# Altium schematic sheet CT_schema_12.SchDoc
size 146 x 119 mm
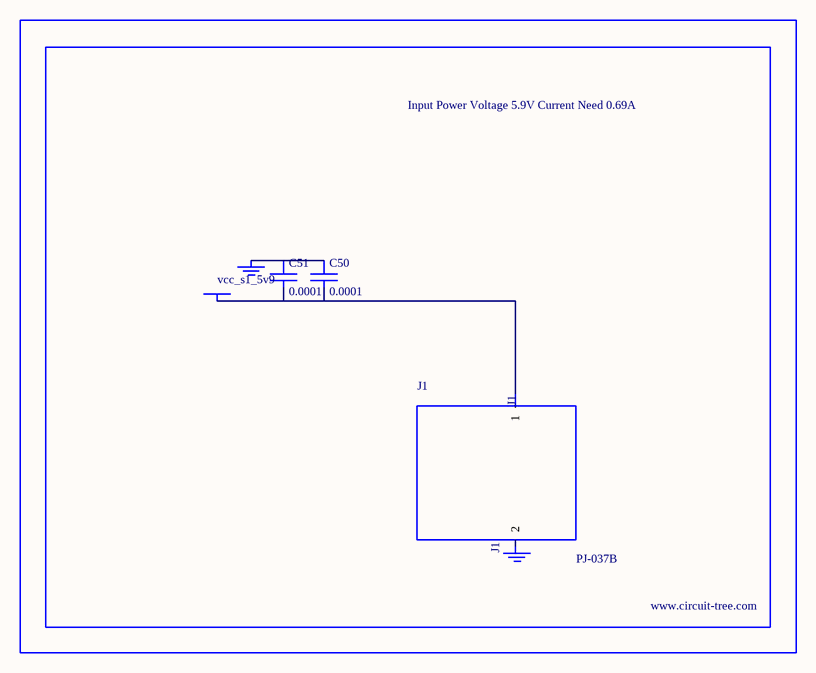
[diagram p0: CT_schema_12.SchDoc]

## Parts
BORDER11  (no value)
C50  0.0001  [EXV-9H]
C51  0.0001  [EXV-9H]
GND_INSTANCE_11_0  (no value)
GND_INSTANCE_11_1  (no value)
J1  PJ-037B  [PJ-037B_PACKAGE]
POWER_INSTANCE_11_0  vcc_s1_5v9

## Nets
NetC50_1: C50.1 C51.1 GND_INSTANCE_11_0.0(GND)
NetC50_2: C50.2 C51.2 J1.1 POWER_INSTANCE_11_0.0(PWR)

Not connected (* = marked no-connect by the designer): GND_INSTANCE_11_1 0(GND); J1 2

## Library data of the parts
BORDER11 = BORDER_PAGE11
C50 C51 = EDK107M035A9HAA
GND_INSTANCE_11_0 GND_INSTANCE_11_1 = GND
POWER_INSTANCE_11_0 = PWR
